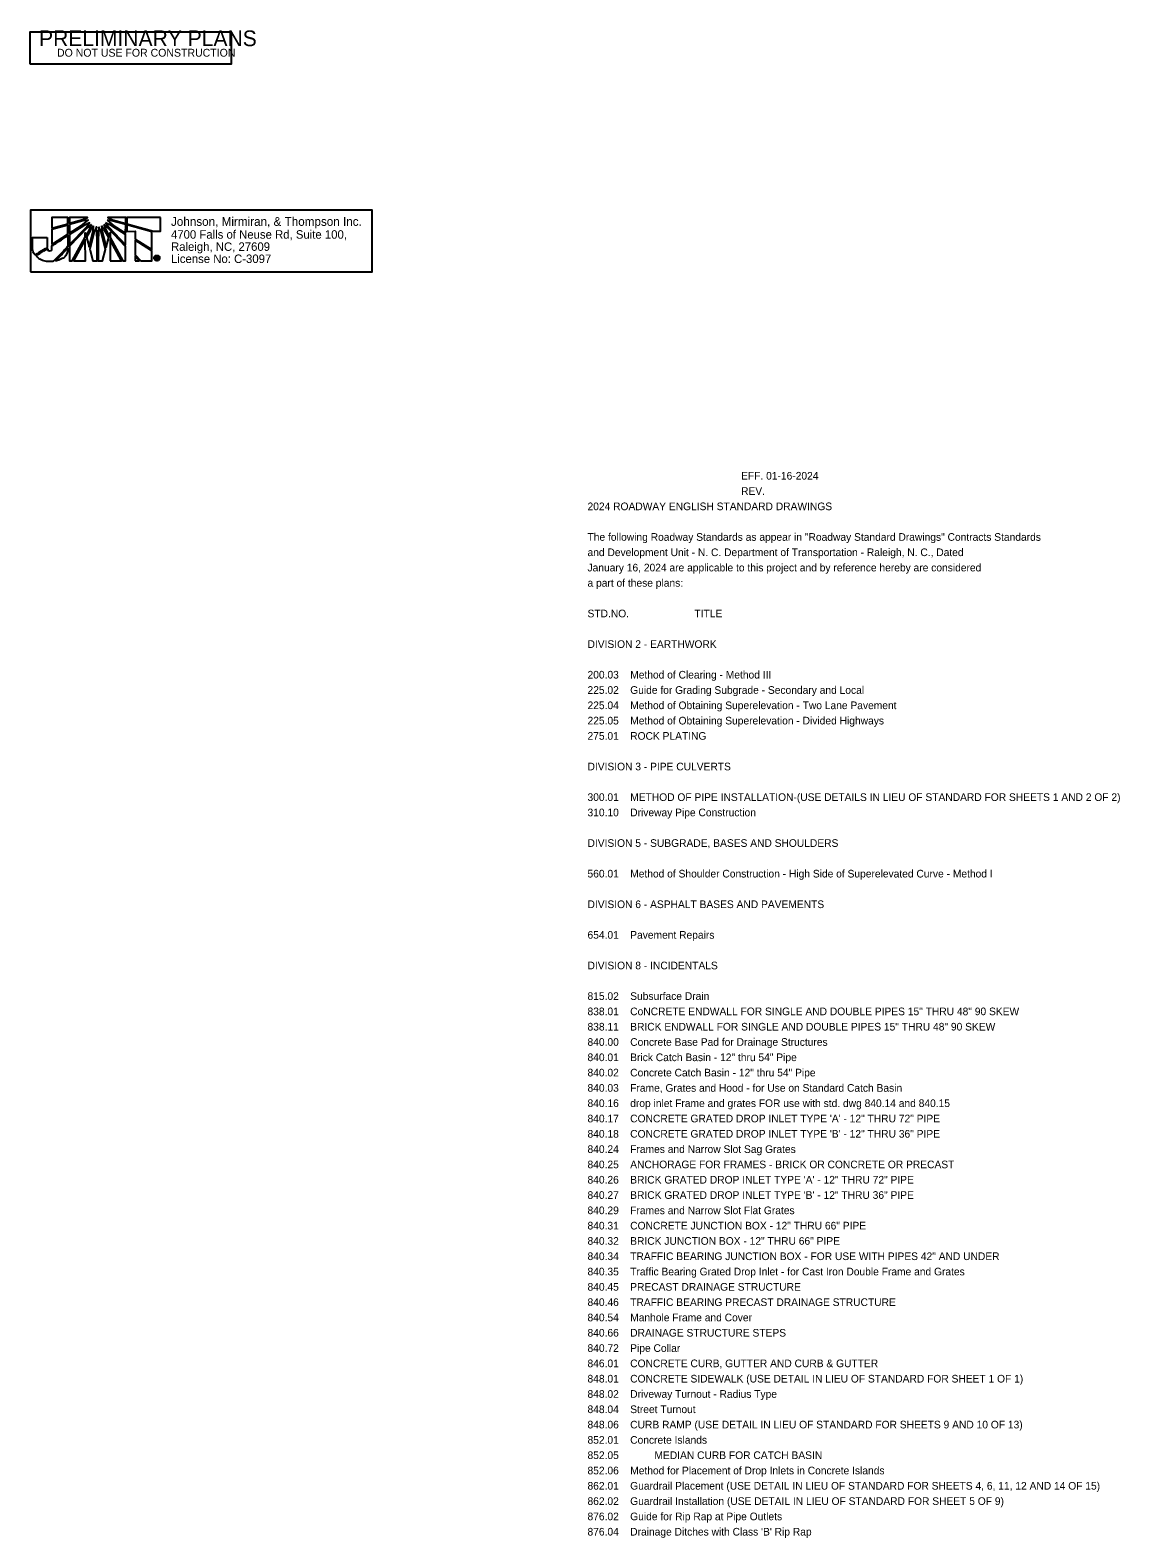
# Model space of a CAD drawing. Extents: x 573687 to 576329, y -53413 to -52265.
# Drawn here: x 575531 to 576329, y -53413 to -52310 of the extents above; entities that cross this region are included whole.
import ezdxf

# ---------------------------------------------------------------- set-up
doc = ezdxf.new("R2010")
doc.units = 0
for name, color, linetype in [('Default', 7, 'Continuous'), ('Sheet Data Text CELL', 7, 'Continuous'), ('Sheet Sticker Preliminary CELL', 7, 'Continuous')]:
    doc.layers.add(name, color=color, linetype=linetype)

msp = doc.modelspace()

# ---------------------------------------------------------------- linework, layer by layer
at = {"layer": 'Default'}
for p, q in [((575559.1, -52446.8), (575547.4, -52446.8)), ((575547.4, -52446.8), (575547.4, -52454.6)), ((575547.4, -52454.6), (575559.1, -52451.3)), ((575559.1, -52452.2), (575547.4, -52455.5)), ((575559.1, -52451.3), (575559.1, -52446.8)), ((575559.1, -52459), (575559.1, -52452.2)), ((575573.5, -52446.7), (575560.3, -52446.8)), ((575560.3, -52446.8), (575560.3, -52450.9)), ((575560.3, -52450.9), (575570.1, -52448.2)), ((575570.1, -52449.1), (575560.3, -52451.9)), ((575560.3, -52451.9), (575560.3, -52458.2)), ((575560.3, -52458.2), (575569.1, -52452.6)), ((575570.4, -52452.7), (575560.3, -52459.2)), ((575560.3, -52466.5), (575572.6, -52453.7)), ((575573.1, -52454.3), (575560.3, -52467.7)), ((575569.1, -52452.6), (575573.9, -52448.7)), ((575570.1, -52448.2), (575573.5, -52446.7)), ((575573.9, -52448.7), (575570.1, -52449.1)), ((575574.9, -52450.5), (575570.4, -52452.7)), ((575572.6, -52453.7), (575574.9, -52450.5)), ((575576.3, -52451.9), (575573.1, -52454.3)), ((575574.8, -52455.6), (575576.3, -52451.9)), ((575577.9, -52452.9), (575575.6, -52455.9)), ((575577.6, -52456.5), (575577.9, -52452.9)), ((575579.9, -52453.5), (575578.3, -52457.2)), ((575580.4, -52462.7), (575579.9, -52453.5)), ((575581.8, -52453.5), (575581.2, -52462.7)), ((575583.3, -52457.2), (575581.8, -52453.5)), ((575583.7, -52452.9), (575584.1, -52456.7)), ((575585.9, -52455.9), (575583.7, -52452.9)), ((575585.3, -52451.9), (575586.8, -52455.6)), ((575588.4, -52454.3), (575585.3, -52451.9)), ((575586.7, -52450.5), (575589, -52453.7)), ((575591.2, -52452.7), (575586.7, -52450.5)), ((575587.7, -52448.7), (575592.6, -52452.7)), ((575591.3, -52449.1), (575587.7, -52448.7)), ((575601.4, -52446.8), (575588.4, -52446.7)), ((575588.4, -52446.7), (575591.7, -52448.3)), ((575601.3, -52467.8), (575588.4, -52454.3)), ((575589, -52453.7), (575601.3, -52466.6)), ((575601.3, -52459.1), (575591.2, -52452.7)), ((575601.4, -52451.9), (575591.3, -52449.1)), ((575591.7, -52448.3), (575601.4, -52451)), ((575592.6, -52452.7), (575601.3, -52458.1)), ((575601.3, -52458.1), (575601.4, -52451.9)), ((575601.4, -52451), (575601.4, -52446.8)), ((575626.9, -52446.7), (575602.3, -52446.7)), ((575602.3, -52446.7), (575602.3, -52451.2)), ((575602.3, -52451.2), (575602.3, -52451.4)), ((575602.3, -52451.4), (575621.6, -52456.8)), ((575602.3, -52452.1), (575602.3, -52452.1)), ((575602.3, -52452.1), (575602.3, -52456.9)), ((575620.4, -52457.2), (575602.3, -52452.1)), ((575626.9, -52456.8), (575626.9, -52446.7)), ((575547.4, -52455.5), (575547.4, -52466.4)), ((575547.4, -52466.4), (575559.1, -52459)), ((575560.3, -52459.2), (575560.3, -52466.5)), ((575562.3, -52478.4), (575571.8, -52461.1)), ((575571.8, -52462.8), (575563.2, -52478.4)), ((575571.8, -52461.1), (575571.8, -52458)), ((575571.8, -52458), (575572.4, -52460.1)), ((575571.9, -52478.4), (575571.8, -52462.8)), ((575572.4, -52460.1), (575574.8, -52455.6)), ((575575.6, -52455.9), (575572.7, -52461.2)), ((575572.7, -52461.2), (575574.6, -52468.2)), ((575574.6, -52468.2), (575577.6, -52456.5)), ((575578.3, -52457.2), (575575, -52469.9)), ((575580.4, -52478.3), (575580.4, -52462.7)), ((575581.2, -52462.7), (575581.2, -52478.3)), ((575586.7, -52470), (575583.3, -52457.2)), ((575584.1, -52456.7), (575587.1, -52468.5)), ((575589, -52461.4), (575585.9, -52455.9)), ((575586.8, -52455.6), (575589.3, -52460.3)), ((575587.1, -52468.5), (575589, -52461.4)), ((575589.3, -52460.3), (575589.9, -52458)), ((575589.9, -52458), (575589.9, -52461.4)), ((575589.9, -52461.4), (575599.2, -52478.3)), ((575598.3, -52478.3), (575589.9, -52463.1)), ((575589.9, -52463.1), (575589.9, -52478.3)), ((575601.3, -52466.6), (575601.3, -52459.1)), ((575602.3, -52456.9), (575608.3, -52456.8)), ((575608.3, -52456.8), (575608.3, -52462.5)), ((575608.3, -52462.5), (575620.4, -52470.1)), ((575608.3, -52463.4), (575608.3, -52473.9)), ((575620.4, -52471), (575608.3, -52463.4)), ((575620.4, -52470.1), (575620.4, -52457.2)), ((575621.6, -52456.8), (575626.9, -52456.8)), ((575560.3, -52467.7), (575560.3, -52478.4)), ((575575, -52469.9), (575577.2, -52478.3)), ((575584.5, -52478.3), (575586.7, -52470)), ((575601.3, -52478.3), (575601.3, -52467.8)), ((575608.3, -52473.9), (575612.5, -52478.3)), ((575611.3, -52478.3), (575608.3, -52475)), ((575608.3, -52475), (575608.3, -52478.3)), ((575620.4, -52478.3), (575620.4, -52471)), ((575623.5, -52477.2), (575623.5, -52475.4)), ((575623.5, -52475.4), (575624.2, -52475.4)), ((575623.9, -52477.2), (575623.5, -52477.2)), ((575624.2, -52475.8), (575623.9, -52475.8)), ((575623.9, -52475.8), (575623.9, -52476.2)), ((575623.9, -52476.2), (575624.2, -52476.2)), ((575624.2, -52476.5), (575623.9, -52476.5)), ((575623.9, -52476.5), (575623.9, -52477.2)), ((575624.2, -52474.4), (575624.2, -52474.7)), ((575624.2, -52474.7), (575624.2, -52474.4)), ((575624.2, -52475.4), (575624.2, -52475.8)), ((575624.2, -52475.8), (575624.2, -52475.4)), ((575624.2, -52475.4), (575624.3, -52475.4)), ((575624.3, -52475.8), (575624.2, -52475.8)), ((575624.2, -52476.2), (575624.2, -52476.5)), ((575624.2, -52476.5), (575624.2, -52476.2)), ((575624.2, -52476.2), (575624.3, -52476.2)), ((575624.3, -52476.5), (575624.2, -52476.5)), ((575560.3, -52478.4), (575562.3, -52478.4)), ((575563.2, -52478.4), (575571.9, -52478.4)), ((575577.2, -52478.3), (575580.4, -52478.3)), ((575581.2, -52478.3), (575584.5, -52478.3)), ((575589.9, -52478.3), (575598.3, -52478.3)), ((575599.2, -52478.3), (575601.3, -52478.3)), ((575608.3, -52478.3), (575611.3, -52478.3)), ((575612.5, -52478.3), (575620.4, -52478.3)), ((575624.2, -52477.9), (575624.2, -52478.3)), ((575624.2, -52478.3), (575624.2, -52477.9)), ((575624.2, -52477.9), (575624.3, -52477.9)), ((575624.3, -52478.3), (575624.2, -52478.3))]:
    msp.add_line(p, q, dxfattribs=at)
msp.add_lwpolyline([(575531.6, -52486.4), (575781.6, -52486.4), (575781.6, -52441.3), (575531.6, -52441.3)], close=True, dxfattribs=at)
for points in [[(575547.4, -52454.6), (575559.1, -52451.3), (575559.1, -52446.8), (575547.4, -52446.8), (575547.4, -52454.6)], [(575547.4, -52466.4), (575559.1, -52459), (575559.1, -52452.2), (575547.4, -52455.5), (575547.4, -52466.4)], [(575570.1, -52448.2), (575573.5, -52446.7), (575560.3, -52446.8), (575560.3, -52450.9), (575570.1, -52448.2)], [(575560.3, -52451.9), (575560.3, -52458.2), (575569.1, -52452.6), (575573.9, -52448.7), (575570.1, -52449.1), (575560.3, -52451.9)], [(575560.3, -52459.2), (575560.3, -52466.5), (575572.6, -52453.7), (575574.9, -52450.5), (575570.4, -52452.7), (575560.3, -52459.2)], [(575576.3, -52451.9), (575573.1, -52454.3), (575560.3, -52467.7), (575560.3, -52478.4), (575562.3, -52478.4), (575571.8, -52461.1), (575571.8, -52458), (575572.4, -52460.1), (575574.8, -52455.6), (575576.3, -52451.9)], [(575577.9, -52452.9), (575575.6, -52455.9), (575572.7, -52461.2), (575574.6, -52468.2), (575577.6, -52456.5), (575577.9, -52452.9)], [(575578.3, -52457.2), (575575, -52469.9), (575577.2, -52478.3), (575580.4, -52478.3), (575580.4, -52462.7), (575579.9, -52453.5), (575578.3, -52457.2)], [(575581.8, -52453.5), (575581.2, -52462.7), (575581.2, -52478.3), (575584.5, -52478.3), (575586.7, -52470), (575583.3, -52457.2), (575581.8, -52453.5)], [(575583.7, -52452.9), (575584.1, -52456.7), (575587.1, -52468.5), (575589, -52461.4), (575585.9, -52455.9), (575583.7, -52452.9)], [(575585.3, -52451.9), (575586.8, -52455.6), (575589.3, -52460.3), (575589.9, -52458), (575589.9, -52461.4), (575599.2, -52478.3), (575601.3, -52478.3), (575601.3, -52467.8), (575588.4, -52454.3), (575585.3, -52451.9)], [(575586.7, -52450.5), (575589, -52453.7), (575601.3, -52466.6), (575601.3, -52459.1), (575591.2, -52452.7), (575586.7, -52450.5)], [(575587.7, -52448.7), (575592.6, -52452.7), (575601.3, -52458.1), (575601.4, -52451.9), (575591.3, -52449.1), (575587.7, -52448.7)], [(575591.7, -52448.3), (575601.4, -52451), (575601.4, -52446.8), (575588.4, -52446.7), (575591.7, -52448.3)], [(575626.9, -52446.7), (575602.3, -52446.7), (575602.3, -52451.2), (575602.3, -52451.4), (575621.6, -52456.8), (575626.9, -52456.8), (575626.9, -52446.7)], [(575602.3, -52452.1), (575602.3, -52452.1), (575602.3, -52456.9), (575608.3, -52456.8), (575608.3, -52462.5), (575620.4, -52470.1), (575620.4, -52457.2), (575602.3, -52452.1)], [(575563.2, -52478.4), (575571.9, -52478.4), (575571.8, -52462.8), (575563.2, -52478.4)], [(575589.9, -52478.3), (575598.3, -52478.3), (575589.9, -52463.1), (575589.9, -52478.3)], [(575608.3, -52463.4), (575608.3, -52473.9), (575612.5, -52478.3), (575620.4, -52478.3), (575620.4, -52471), (575608.3, -52463.4), (575608.3, -52463.4)], [(575608.3, -52478.3), (575608.3, -52478.3), (575611.3, -52478.3), (575608.3, -52475), (575608.3, -52478.3)], [(575625, -52476.8), (575625, -52476.9), (575625, -52476.9), (575625, -52477), (575625.1, -52477.2), (575624.7, -52477.2)]]:
    msp.add_lwpolyline(points, dxfattribs=at)
for points, degree in [([(575544, -52461.4), (575544, -52461.4), (575533.2, -52461.4), (575533.2, -52461.4), (575533.2, -52461.4), (575533.2, -52468.2), (575533.2, -52468.2), (575533.2, -52468.2), (575533.2, -52468.9), (575533.2, -52468.9), (575533.2, -52471), (575533.9, -52472.7), (575535.1, -52474.1), (575535.1, -52474.1), (575544, -52468.7), (575544, -52468.5), (575544, -52468.5), (575544, -52461.4), (575544, -52461.4)], 3), ([(575545.7, -52471.1), (575545, -52471.1), (575544.4, -52470.7), (575544.2, -52469.4), (575544.2, -52469.4), (575535.8, -52474.6), (575535.8, -52474.6), (575538.4, -52477.4), (575542.5, -52479), (575546, -52479), (575546.9, -52479), (575547.6, -52478.9), (575548.6, -52478.7), (575548.6, -52478.7), (575559.1, -52467.8), (575559.1, -52467.8), (575559.1, -52467.8), (575559.1, -52459.9), (575559.1, -52459.9), (575559.1, -52459.9), (575547.4, -52467.4), (575547.4, -52467.4), (575547.4, -52470.3), (575546.7, -52471.1), (575545.7, -52471.1)], 3), ([(575545.7, -52471.1), (575545, -52471.1), (575544.4, -52470.7), (575544.2, -52469.4), (575544.2, -52469.4), (575535.8, -52474.6), (575535.8, -52474.6), (575538.4, -52477.4), (575542.5, -52479), (575546, -52479), (575546.9, -52479), (575547.6, -52478.9), (575548.6, -52478.7), (575548.6, -52478.7), (575559.1, -52467.8), (575559.1, -52467.8), (575559.1, -52467.8), (575559.1, -52459.9), (575559.1, -52459.9), (575559.1, -52459.9), (575547.4, -52467.4), (575547.4, -52467.4), (575547.4, -52470.3), (575546.7, -52471.1), (575545.7, -52471.1)], 3), ([(575559.1, -52469), (575559.1, -52469), (575550, -52478.5), (575550, -52478.5), (575554.5, -52477.3), (575558.9, -52474.4), (575559.1, -52469)], 3), ([(575624.2, -52478.3), (575623.7, -52478.3), (575623.2, -52478.1), (575622.8, -52477.7), (575622.4, -52477.3), (575622.2, -52476.9), (575622.2, -52476.3), (575622.2, -52475.8), (575622.4, -52475.3), (575622.8, -52474.9), (575623.2, -52474.5), (575623.7, -52474.4), (575624.2, -52474.4)], 3), ([(575624.2, -52474.7), (575623.8, -52474.7), (575623.4, -52474.9), (575623.1, -52475.2), (575622.8, -52475.5), (575622.6, -52475.9), (575622.6, -52476.3), (575622.6, -52476.7), (575622.8, -52477.1), (575623.1, -52477.4), (575623.4, -52477.8), (575623.8, -52477.9), (575624.2, -52477.9)], 3), ([(575624.2, -52474.4), (575624.8, -52474.4), (575625.3, -52474.5), (575625.6, -52474.9), (575626, -52475.3), (575626.2, -52475.7), (575626.2, -52476.3)], 3), ([(575624.3, -52477.9), (575624.7, -52477.9), (575625.1, -52477.7), (575625.4, -52477.4), (575625.7, -52477.1), (575625.8, -52476.7), (575625.8, -52476.3), (575625.8, -52475.9), (575625.7, -52475.5), (575625.4, -52475.2), (575625.1, -52474.9), (575624.7, -52474.7), (575624.2, -52474.7)], 3), ([(575624.3, -52475.4), (575624.8, -52475.4), (575625, -52475.6), (575625, -52475.9), (575625, -52476.1), (575625, -52476.2), (575624.8, -52476.3)], 3), ([(575624.3, -52476.2), (575624.5, -52476.2), (575624.6, -52476.1), (575624.6, -52475.9), (575624.6, -52475.8), (575624.5, -52475.8), (575624.3, -52475.8)], 3), ([(575626.2, -52476.3), (575626.2, -52476.9), (575626, -52477.3), (575625.7, -52477.7), (575625.3, -52478.1), (575624.8, -52478.3), (575624.3, -52478.3)], 3), ([(575624.6, -52476.6), (575624.5, -52476.5), (575624.4, -52476.5), (575624.3, -52476.5)], 2), ([(575624.7, -52477.2), (575624.7, -52477.1), (575624.6, -52477), (575624.6, -52476.9), (575624.6, -52476.7), (575624.6, -52476.6), (575624.6, -52476.6)], 3), ([(575624.8, -52476.3), (575624.9, -52476.4), (575625, -52476.5), (575625, -52476.8)], 2)]:
    msp.add_open_spline(points, degree=degree, dxfattribs=at)
at = {"layer": 'Sheet Sticker Preliminary CELL'}
msp.add_lwpolyline([(575531.5, -52334.4), (575531.5, -52310.9), (575678.5, -52310.9), (575678.5, -52334.4)], close=True, dxfattribs=at)

# ---------------------------------------------------------------- texts
at = {"layer": 'Default'}
for s, height, p in [('Johnson, Mirmiran, & Thompson Inc.', 6.389, (575634.5, -52452.8)), ('4700 Falls of Neuse Rd, Suite 100, ', 6.206, (575634.5, -52462.2)), ('Raleigh, NC, 27609', 6.206, (575634.5, -52471.1)), ('License No: C-3097', 6.206, (575634.5, -52480))]:
    msp.add_text(s, height=height, dxfattribs=at).set_placement(p)
at = {"layer": 'Sheet Data Text CELL'}
for s, p in [('                                                      EFF. 01-16-2024', (575939.2, -52638.5)), ('                                                      REV. ', (575939.2, -52649.7)), ('2024 ROADWAY ENGLISH STANDARD DRAWINGS', (575939.2, -52660.9)), ('The following Roadway Standards as appear in "Roadway Standard Drawings" Contracts Standards ', (575939.2, -52683.3)), ('and Development Unit - N. C. Department of Transportation - Raleigh, N. C., Dated ', (575939.2, -52694.5)), ('January 16, 2024 are applicable to this project and by reference hereby are considered ', (575939.2, -52705.7)), ('a part of these plans:', (575939.2, -52716.9)), ('STD.NO.                       TITLE', (575939.2, -52739.3)), ('DIVISION 2 - EARTHWORK', (575939.2, -52761.7)), ('200.03    Method of Clearing - Method III', (575939.2, -52784.1)), ('225.02    Guide for Grading Subgrade - Secondary and Local', (575939.2, -52795.3)), ('225.04    Method of Obtaining Superelevation - Two Lane Pavement', (575939.2, -52806.5)), ('225.05    Method of Obtaining Superelevation - Divided Highways', (575939.2, -52817.7)), ('275.01    ROCK PLATING', (575939.2, -52828.9)), ('DIVISION 3 - PIPE CULVERTS', (575939.2, -52851.3)), ('300.01    METHOD OF PIPE INSTALLATION-(USE DETAILS IN LIEU OF STANDARD FOR SHEETS 1 AND 2 OF 2) ', (575939.2, -52873.7)), ('310.10    Driveway Pipe Construction', (575939.2, -52884.9)), ('DIVISION 5 - SUBGRADE, BASES AND SHOULDERS', (575939.2, -52907.3)), ('560.01    Method of Shoulder Construction - High Side of Superelevated Curve - Method I', (575939.2, -52929.7)), ('DIVISION 6 - ASPHALT BASES AND PAVEMENTS', (575939.2, -52952.1)), ('654.01    Pavement Repairs', (575939.2, -52974.5)), ('DIVISION 8 - INCIDENTALS', (575939.2, -52996.9)), ('815.02    Subsurface Drain', (575939.2, -53019.3)), ('838.01    CoNCRETE ENDWALL FOR SINGLE AND DOUBLE PIPES 15" THRU 48" 90 SKEW  ', (575939.2, -53030.5)), ('838.11    BRICK ENDWALL FOR SINGLE AND DOUBLE PIPES 15" THRU 48" 90 SKEW', (575939.2, -53041.7)), ('840.00    Concrete Base Pad for Drainage Structures', (575939.2, -53052.9)), ('840.01    Brick Catch Basin - 12" thru 54" Pipe', (575939.2, -53064.1)), ('840.02    Concrete Catch Basin - 12" thru 54" Pipe', (575939.2, -53075.3)), ('840.03    Frame, Grates and Hood - for Use on Standard Catch Basin', (575939.2, -53086.5)), ('840.16    drop inlet Frame and grates FOR use with std. dwg 840.14 and 840.15 ', (575939.2, -53097.7)), ('840.17    CONCRETE GRATED DROP INLET TYPE \'A\' - 12" THRU 72" PIPE', (575939.2, -53108.9)), ('840.18    CONCRETE GRATED DROP INLET TYPE \'B\' - 12" THRU 36" PIPE', (575939.2, -53120.1)), ('840.24    Frames and Narrow Slot Sag Grates', (575939.2, -53131.3)), ('840.25    ANCHORAGE FOR FRAMES - BRICK OR CONCRETE OR PRECAST', (575939.2, -53142.5)), ('840.26    BRICK GRATED DROP INLET TYPE \'A\' - 12" THRU 72" PIPE', (575939.2, -53153.7)), ('840.27    BRICK GRATED DROP INLET TYPE \'B\' - 12" THRU 36" PIPE', (575939.2, -53164.9)), ('840.29    Frames and Narrow Slot Flat Grates', (575939.2, -53176.1)), ('840.31    CONCRETE JUNCTION BOX - 12" THRU 66" PIPE', (575939.2, -53187.3)), ('840.32    BRICK JUNCTION BOX - 12" THRU 66" PIPE', (575939.2, -53198.5)), ('840.34    TRAFFIC BEARING JUNCTION BOX - FOR USE WITH PIPES 42" AND UNDER', (575939.2, -53209.7)), ('840.35    Traffic Bearing Grated Drop Inlet - for Cast Iron Double Frame and Grates', (575939.2, -53220.9)), ('840.45    PRECAST DRAINAGE STRUCTURE', (575939.2, -53232.1)), ('840.46    TRAFFIC BEARING PRECAST DRAINAGE STRUCTURE', (575939.2, -53243.3)), ('840.54    Manhole Frame and Cover', (575939.2, -53254.5)), ('840.66    DRAINAGE STRUCTURE STEPS', (575939.2, -53265.7)), ('840.72    Pipe Collar', (575939.2, -53276.9)), ('846.01    CONCRETE CURB, GUTTER AND CURB & GUTTER', (575939.2, -53288.1)), ('848.01    CONCRETE SIDEWALK (USE DETAIL IN LIEU OF STANDARD FOR SHEET 1 OF 1)', (575939.2, -53299.3)), ('848.02    Driveway Turnout - Radius Type', (575939.2, -53310.5)), ('848.04    Street Turnout', (575939.2, -53321.7)), ('848.06    CURB RAMP (USE DETAIL IN LIEU OF STANDARD FOR SHEETS 9 AND 10 OF 13)', (575939.2, -53332.9)), ('852.01    Concrete Islands', (575939.2, -53344.1)), ('852.05', (575939.2, -53355.3)), ('  MEDIAN CURB FOR CATCH BASIN', (575984, -53355.3)), ('852.06    Method for Placement of Drop Inlets in Concrete Islands', (575939.2, -53366.5)), ('862.01    Guardrail Placement (USE DETAIL IN LIEU OF STANDARD FOR SHEETS 4, 6, 11, 12 AND 14 OF 15)', (575939.2, -53377.7)), ('862.02    Guardrail Installation (USE DETAIL IN LIEU OF STANDARD FOR SHEET 5 OF 9)', (575939.2, -53388.9)), ('876.02    Guide for Rip Rap at Pipe Outlets', (575939.2, -53400.1)), ("876.04    Drainage Ditches with Class 'B' Rip Rap", (575939.2, -53411.3))]:
    msp.add_text(s, height=5.6, dxfattribs=at).set_placement(p)
at = {"layer": 'Sheet Sticker Preliminary CELL'}
for s, height, p in [('PRELIMINARY PLANS', 11.52, (575538, -52321.3)), ('DO NOT USE FOR CONSTRUCTION', 5.76, (575551.1, -52329))]:
    msp.add_text(s, height=height, dxfattribs=at).set_placement(p)

doc.saveas('drawing.dxf')
